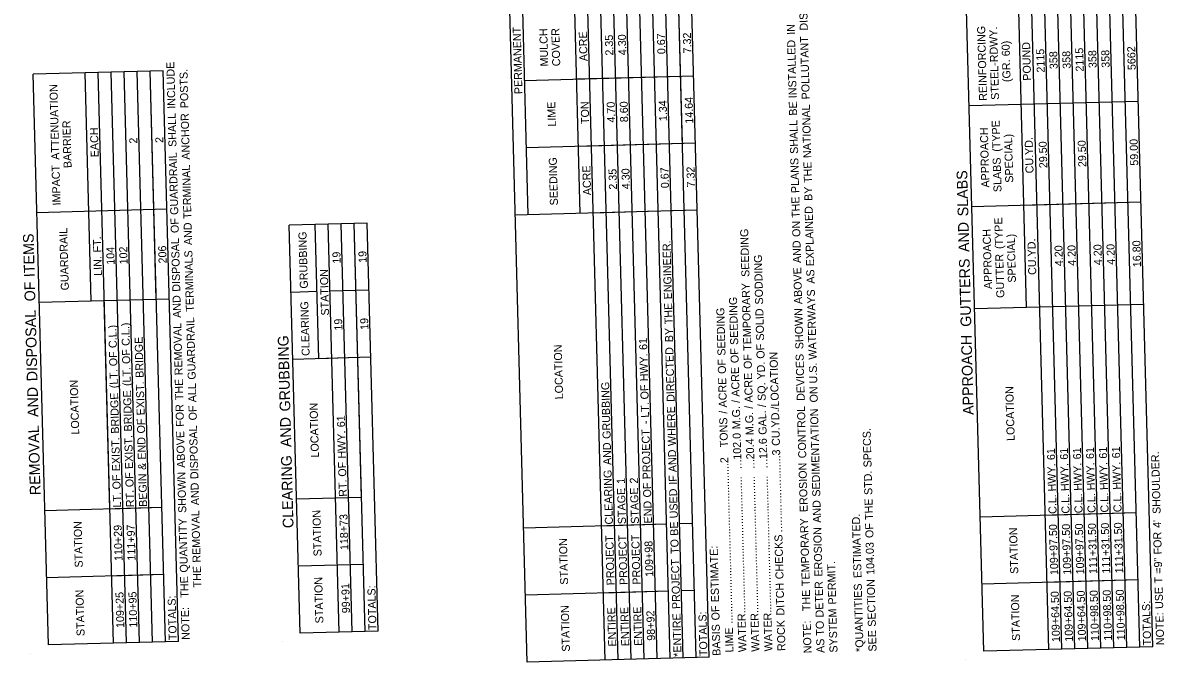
# Model space of a CAD drawing. Extents: x 1930093 to 1931323, y 596452 to 607874.
# Drawn here: x 1930227 to 1931083, y 601457 to 601936 of the extents above; entities that cross this region are included whole.
import ezdxf

# ---------------------------------------------------------------- set-up
doc = ezdxf.new("R2010")
doc.units = 0
doc.layers.add('Default', color=7, linetype='Continuous')
doc.layers.add('R_Border', color=7, linetype='Continuous')

msp = doc.modelspace()

# ---------------------------------------------------------------- linework, layer by layer
at = {"layer": 'Default'}
for p, q in [((1930605.63, 601457.38), (1930573.54, 602652.78)), ((1930606.39, 601792.43), (1930583.29, 602653.05)), ((1930645.38, 601793.48), (1930622.28, 602654.09)), ((1930664.11, 601458.95), (1930632.02, 602654.35)), ((1930673.86, 601459.21), (1930641.77, 602654.62)), ((1930683.6, 601459.47), (1930651.52, 602654.88)), ((1930693.35, 601459.73), (1930661.26, 602655.14)), ((1930703.1, 601459.99), (1930671.01, 602655.4)), ((1930712.84, 601460.26), (1930680.75, 602655.66)), ((1930722.59, 601460.52), (1930690.5, 602655.92)), ((1930732.34, 601460.78), (1930700.25, 602656.19)), ((1930742.08, 601461.04), (1930709.99, 602656.45)), ((1930722, 601845.77), (1930716.17, 602063.11)), ((1930948, 601465.56), (1930933.5, 602006)), ((1930980.11, 601722.94), (1930972.48, 602007.05)), ((1930996.74, 601466.87), (1930982.23, 602007.31)), ((1931006.48, 601467.13), (1930991.97, 602007.57)), ((1931016.23, 601467.39), (1931001.72, 602007.84)), ((1931025.97, 601467.66), (1931011.47, 602008.1)), ((1931035.72, 601467.92), (1931021.21, 602008.36)), ((1931045.47, 601468.18), (1931030.96, 602008.62)), ((1931055.21, 601468.44), (1931040.71, 602008.88)), ((1931064.96, 601468.7), (1931050.45, 602009.14)), ((1931074.71, 601468.96), (1931060.2, 602009.41)), ((1930332.61, 601900.35), (1930235.14, 601897.73)), ((1930278.72, 601727.73), (1930274.13, 601898.78)), ((1930295.35, 601471.66), (1930283.88, 601899.04)), ((1930305.1, 601471.92), (1930293.62, 601899.3)), ((1930314.84, 601472.18), (1930303.37, 601899.56)), ((1930324.59, 601472.44), (1930313.12, 601899.82)), ((1930334.34, 601472.7), (1930322.86, 601900.09)), ((1930325.65, 601796.29), (1930322.86, 601900.09)), ((1930344.08, 601472.96), (1930332.61, 601900.35)), ((1930246.62, 601470.35), (1930235.14, 601897.73)), ((1930730.4, 601896.22), (1930603.7, 601892.82)), ((1930720.66, 601895.96), (1930642.68, 601893.87)), ((1931063.74, 601877.34), (1930937.04, 601873.94)), ((1931063.74, 601877.34), (1930976.03, 601874.99)), ((1930731.75, 601846.03), (1930605.04, 601842.63)), ((1930731.75, 601846.03), (1930644.03, 601843.67)), ((1930335.4, 601796.55), (1930237.93, 601793.93)), ((1930327.45, 601729.04), (1930325.65, 601796.29)), ((1930733.1, 601795.83), (1930596.65, 601792.17)), ((1930733.1, 601795.83), (1930713.6, 601795.31)), ((1931065.77, 601801.81), (1930939.07, 601798.4)), ((1931065.77, 601801.81), (1930978.05, 601799.45)), ((1930703.86, 601795.05), (1930655.12, 601793.74)), ((1930485.67, 601786.1), (1930427.19, 601784.53)), ((1930446.69, 601785.05), (1930427.19, 601784.53)), ((1930435.4, 601478.97), (1930427.19, 601784.53)), ((1930449.38, 601684.66), (1930446.69, 601785.05)), ((1930475.93, 601785.83), (1930456.43, 601785.31)), ((1930464.64, 601479.76), (1930456.43, 601785.31)), ((1930474.38, 601480.02), (1930466.18, 601785.57)), ((1930484.13, 601480.28), (1930475.93, 601785.83)), ((1930481.43, 601580.67), (1930475.93, 601785.83)), ((1930493.88, 601480.54), (1930485.67, 601786.1)), ((1930487.02, 601735.9), (1930457.78, 601735.12)), ((1930487.02, 601735.9), (1930457.78, 601735.12)), ((1930337.2, 601729.3), (1930239.74, 601726.68)), ((1930292.65, 601572.05), (1930288.47, 601727.99)), ((1930337.2, 601729.3), (1930327.45, 601729.04)), ((1930448.04, 601734.85), (1930428.54, 601734.33)), ((1931067.83, 601725.3), (1930941.12, 601721.89)), ((1931067.83, 601725.3), (1930989.85, 601723.2)), ((1930488.37, 601685.71), (1930429.89, 601684.14)), ((1930478.62, 601685.45), (1930449.38, 601684.66)), ((1930331.64, 601573.09), (1930243.92, 601570.74)), ((1930331.64, 601573.09), (1930292.65, 601572.05)), ((1930481.43, 601580.67), (1930432.7, 601579.36)), ((1930481.43, 601580.67), (1930461.94, 601580.15)), ((1931062.27, 601569.09), (1930945.31, 601565.95)), ((1931062.27, 601569.09), (1930994.04, 601567.26)), ((1930710.15, 601560.64), (1930602.94, 601557.77)), ((1930710.15, 601560.64), (1930661.42, 601559.34)), ((1930729.64, 601561.17), (1930719.9, 601560.91)), ((1930729.64, 601561.17), (1930719.9, 601560.91)), ((1930482.78, 601530.48), (1930434.05, 601529.17)), ((1930482.78, 601530.48), (1930463.29, 601529.95)), ((1930332.99, 601522.9), (1930245.27, 601520.54)), ((1930332.99, 601522.9), (1930294, 601521.85)), ((1931063.61, 601518.9), (1930946.66, 601515.76)), ((1931063.61, 601518.9), (1930995.39, 601517.06)), ((1930711.5, 601510.45), (1930604.29, 601507.57)), ((1930711.5, 601510.45), (1930662.76, 601509.14)), ((1930730.99, 601510.97), (1930721.24, 601510.71)), ((1930730.99, 601510.97), (1930721.24, 601510.71)), ((1930493.88, 601480.54), (1930435.4, 601478.97)), ((1930493.88, 601480.54), (1930435.4, 601478.97)), ((1930344.08, 601472.96), (1930246.62, 601470.35)), ((1930344.08, 601472.96), (1930246.62, 601470.35)), ((1931074.71, 601468.96), (1930948, 601465.56)), ((1931074.71, 601468.96), (1930948, 601465.56)), ((1930742.08, 601461.04), (1930605.63, 601457.38)), ((1930742.08, 601461.04), (1930605.63, 601457.38))]:
    msp.add_line(p, q, dxfattribs=at)
at = {"layer": 'R_Border'}
for p, q in [((1930421.91, 601472.76), (1930421.91, 601472.76)), ((1930233.13, 601464.13), (1930233.13, 601464.13)), ((1930934.51, 601459.35), (1930934.51, 601459.35))]:
    msp.add_line(p, q, dxfattribs=at)

# ---------------------------------------------------------------- texts
at = {"layer": 'Default'}
for s, height, p in [(' DISCHARGE', 6, (1930816.12, 601928.2)), ('PERMANENT', 6, (1930602.09, 601882.88)), (' IN', 6, (1930806.45, 601925.08)), ('REINFORCING', 6, (1930950.44, 601877.87)), ('STEEL-RDWY.', 6, (1930959.42, 601878.62)), ('MULCH', 6, (1930621.41, 601903.59)), ('COVER', 6, (1930630.41, 601903.76)), ('ACRE', 6, (1930650.87, 601907.53)), ('2.35', 6, (1930670.26, 601911.73)), ('4.30', 6, (1930680.01, 601912.03)), ('0.67', 6, (1930709.25, 601912.8)), ('7.32', 6, (1930728.74, 601913.35)), (' POLLUTANT', 6, (1930817.51, 601876.68)), (' INSTALLED', 6, (1930807.73, 601877.56)), (' 60)', 6, (1930967.61, 601908.99)), ('POUND', 6, (1930983.42, 601892.92)), ('2115', 6, (1930993.69, 601898.98)), ('2115', 6, (1931022.93, 601899.76)), ('358', 6, (1931032.61, 601902.37)), ('358', 6, (1931042.36, 601902.63)), ('5662', 6, (1931061.91, 601900.85)), ('(GR.', 6, (1930968.07, 601891.88)), ('358', 6, (1931003.37, 601901.59)), ('358', 6, (1931013.12, 601901.85)), (' INCLUDE', 6, (1930341.99, 601869.68)), (' POSTS.', 6, (1930351.73, 601870.08)), (' ATTENUATION', 6, (1930254.93, 601831.43)), ('LIME', 6, (1930627.13, 601858.53)), ('TON', 6, (1930652.13, 601860.49)), ('4.70', 6, (1930671.61, 601861.57)), ('8.60', 6, (1930681.36, 601861.83)), ('1.34', 6, (1930710.6, 601862.62)), ('14.64', 6, (1930730.15, 601860.71)), (' BE', 6, (1930808.08, 601864.5)), (' NATIONAL', 6, (1930818.69, 601832.74)), (' SHALL', 6, (1930342.75, 601841.1)), (' ANCHOR', 6, (1930352.76, 601831.55)), ('BARRIER', 6, (1930264.04, 601827.49)), ('EACH', 6, (1930284.38, 601835.56)), (' SHALL', 6, (1930808.85, 601835.91)), ('APPROACH', 6, (1930952.18, 601812.87)), (' (TYPE', 6, (1930960.53, 601837.48)), ('2', 6, (1930313.37, 601845.79)), ('2', 6, (1930332.86, 601846.3)), ('SPECIAL)', 6, (1930970.09, 601816.51)), ('CU.YD.', 6, (1930985.29, 601823.52)), ('29.50', 6, (1930995.61, 601827.43)), ('29.50', 6, (1931024.85, 601828.22)), ('59.00', 6, (1931063.83, 601829.27)), (' GUARDRAIL', 6, (1930344.12, 601790.18)), ('SEEDING', 6, (1930628.71, 601799.52)), (' PLANS', 6, (1930809.64, 601806.54)), (' THE', 6, (1930819.19, 601814.1)), ('SLABS', 6, (1930961.28, 601809.48)), ('IMPACT', 6, (1930255.79, 601799.48)), (' TERMINAL', 6, (1930353.95, 601787.15)), ('ACRE', 6, (1930653.56, 601807.14)), ('2.35', 6, (1930672.96, 601811.34)), ('4.30', 6, (1930682.7, 601811.64)), ('0.67', 6, (1930711.94, 601812.41)), ('7.32', 6, (1930731.44, 601812.96)), (' SLABS', 8, (1930936.51, 601788.39)), (' BY', 6, (1930819.55, 601800.65)), (' THE', 6, (1930810.14, 601787.9)), (' EXPLAINED', 6, (1930820.86, 601751.73)), (' OF', 6, (1930344.48, 601776.59)), (' ON', 6, (1930810.52, 601773.69)), (' (TYPE', 6, (1930962.48, 601764.66)), ('GUARDRAIL', 6, (1930262, 601735.89)), (' AND', 6, (1930354.48, 601767.57)), ('GRUBBING', 6, (1930441.22, 601737.21)), (' SEEDING', 6, (1930772.31, 601743.73)), (' AND', 8, (1930937.23, 601761.63)), ('APPROACH', 6, (1930954.23, 601736.85)), (' ITEMS', 8, (1930236.48, 601742.84)), (' FT.', 6, (1930286.35, 601762.05)), (' DISPOSAL', 6, (1930345.66, 601732.64)), (' ENGINEER.', 6, (1930714.24, 601726.95)), (' AND', 6, (1930811.04, 601754.11)), ('SPECIAL)', 6, (1930972.1, 601741.66)), ('CU.YD.', 6, (1930987.33, 601747.49)), ('4.20', 6, (1931036.57, 601754.78)), ('4.20', 6, (1931046.32, 601755.05)), ('16.80', 6, (1931065.88, 601753.24)), ('104', 6, (1930296.29, 601755.06)), ('102', 6, (1930306.04, 601755.34)), ('206', 6, (1930335.28, 601756.05)), (' TERMINALS', 6, (1930355.82, 601717.72)), ('19', 6, (1930465.78, 601755.97)), ('19', 6, (1930485.27, 601756.5)), (' SODDING', 6, (1930782.62, 601723.06)), ('GUTTER', 6, (1930963.41, 601730.25)), ('4.20', 6, (1931007.33, 601754)), ('4.20', 6, (1931017.08, 601754.26)), ('LIN.', 6, (1930286.76, 601746.8)), (' ABOVE', 6, (1930811.87, 601723.35)), (' GUTTERS', 8, (1930938.73, 601705.68)), ('STATION', 6, (1930457.07, 601717.03)), (' AS', 6, (1930821.21, 601738.66)), (' OF', 8, (1930236.96, 601724.73)), (' TEMPORARY', 6, (1930773.79, 601688.37)), (' WATERWAYS', 6, (1930822.74, 601681.82)), (' AND', 6, (1930346.19, 601713.07)), ('CLEARING', 6, (1930442.57, 601686.78)), (' SEEDING', 6, (1930763.92, 601692.77)), (' DISPOSAL', 8, (1930238.57, 601664.84)), (' THE', 6, (1930714.74, 601708.3)), (' SEEDING', 6, (1930754.39, 601684.71)), (' SOLID', 6, (1930783.34, 601696.04)), (' SHOWN', 6, (1930812.78, 601689.58)), (' C.L.)', 6, (1930307.74, 601692.09)), (' REMOVAL', 6, (1930347.34, 601670.05)), (' GUARDRAIL', 6, (1930357.19, 601666.79)), ('19', 6, (1930467.12, 601705.78)), ('19', 6, (1930486.62, 601706.31)), (' C.L.)', 6, (1930298.03, 601690.43)), (' GRUBBING', 8, (1930428.19, 601642.26)), (' BY', 6, (1930715.1, 601694.86)), ('APPROACH', 8, (1930940.42, 601642.59)), (' BRIDGE', 6, (1930318.13, 601668.19)), ('LOCATION', 6, (1930632.61, 601654.29)), (' 61', 6, (1930695.75, 601689.04)), (' DIRECTED', 6, (1930716.3, 601650.14)), (' OF', 6, (1930783.71, 601682.45)), (' OF', 6, (1930298.39, 601676.85)), (' OF', 6, (1930308.1, 601678.51)), (' HWY.', 6, (1930696.38, 601665.57)), (' OF', 6, (1930764.29, 601679.19)), (' OF', 6, (1930774.16, 601674.79)), (' CU.YD./LOCATION', 6, (1930795.21, 601617.22)), (' DEVICES', 6, (1930813.81, 601650.9)), (' (LT.', 6, (1930298.84, 601660.36)), (' (LT.', 6, (1930308.55, 601662.02)), (' OF', 6, (1930754.75, 601671.13)), (' ACRE', 6, (1930764.96, 601654.03)), (' YD.', 6, (1930784.12, 601666.89)), (' U.S.', 6, (1930823.22, 601663.93)), ('LOCATION', 6, (1930269.77, 601627.9)), (' THE', 6, (1930347.84, 601651.41)), (' ACRE', 6, (1930755.43, 601645.97)), (' ACRE', 6, (1930774.83, 601649.63)), (' AND', 8, (1930239.29, 601638.08)), (' BRIDGE', 6, (1930299.75, 601626.35)), (' BRIDGE', 6, (1930309.46, 601628)), (' EXIST.', 6, (1930318.89, 601640.05)), (' ALL', 6, (1930357.64, 601649.85)), (' GRUBBING', 6, (1930668.28, 601622.43)), (' OF', 6, (1930696.74, 601651.99)), (' SQ.', 6, (1930784.56, 601650.86)), (' ON', 6, (1930823.6, 601649.72)), ('LOCATION', 6, (1930971.16, 601623.11)), (' FOR', 6, (1930348.38, 601631.51)), ('LOCATION', 6, (1930449.49, 601610.68)), (' LT.', 6, (1930697.11, 601638.29)), (' /', 6, (1930765.09, 601649.37)), (' /', 6, (1930784.68, 601646.2)), (' OF', 6, (1930358, 601636.27)), (' 61', 6, (1930469.12, 601631.18)), (' WHERE', 6, (1930717.19, 601617.07)), (' /', 6, (1930755.55, 601641.31)), (' M.G.', 6, (1930765.62, 601629.62)), (' /', 6, (1930774.96, 601644.97)), (' M.G.', 6, (1930775.49, 601625.22)), (' GAL.', 6, (1930785.24, 601625.51)), (' CONTROL', 6, (1930814.97, 601607.9)), (' SEDIMENTATION', 6, (1930825.49, 601579.16)), ('REMOVAL', 8, (1930240.78, 601582.54)), (' OF', 6, (1930319.25, 601626.47)), (' DISPOSAL', 6, (1930359.18, 601592.32)), (' AND', 8, (1930428.91, 601615.5)), (' -', 6, (1930697.24, 601633.43)), (' TONS', 6, (1930756.23, 601616.14)), (' EXIST.', 6, (1930300.51, 601598.21)), (' EXIST.', 6, (1930310.21, 601599.86)), (' END', 6, (1930319.78, 601606.89)), (' ABOVE', 6, (1930349.2, 601600.75)), (' HWY.', 6, (1930469.76, 601607.7)), (' PROJECT', 6, (1930698.35, 601592.16)), ('102.0', 6, (1930766.17, 601609.06)), ('20.4', 6, (1930775.92, 601609.32)), ('12.6', 6, (1930785.66, 601609.58)), (' SPECS.', 6, (1930863.92, 601601.08)), (' AND', 6, (1930668.8, 601602.86)), (' AND', 6, (1930717.71, 601597.49)), ('.......3', 6, (1930795.76, 601596.65)), (' 61', 6, (1931001.54, 601606.57)), (' 61', 6, (1931011.28, 601606.83)), (' 61', 6, (1931021.03, 601607.09)), (' 61', 6, (1931030.78, 601607.36)), (' 61', 6, (1931040.52, 601607.62)), (' 61', 6, (1931050.27, 601607.88)), ('CLEARING', 8, (1930430.45, 601557.82)), (' ......................................................2', 6, (1930759.78, 601483.94)), ('…', 6, (1930766.37, 601601.66)), ('…', 6, (1930776.12, 601601.93)), ('…', 6, (1930785.86, 601602.19)), ('  SHOULDER.', 6, (1931080.71, 601563.99)), (' OF', 6, (1930310.58, 601586.28)), (' &', 6, (1930319.99, 601599.17)), (' SHOWN', 6, (1930350.11, 601566.98)), (' OF', 6, (1930470.12, 601594.12)), ('CLEARING', 6, (1930669.94, 601560.54)), (' EROSION', 6, (1930816.05, 601567.6)), (' STD.', 6, (1930864.47, 601580.39)), (' HWY.', 6, (1931002.17, 601583.1)), (' HWY.', 6, (1931011.91, 601583.36)), (' HWY.', 6, (1931021.66, 601583.62)), (' HWY.', 6, (1931031.41, 601583.88)), (' HWY.', 6, (1931041.15, 601584.14)), (' HWY.', 6, (1931050.9, 601584.4)), (' OF', 6, (1930300.87, 601584.62)), ('BEGIN', 6, (1930320.67, 601573.77)), (' AND', 6, (1930359.71, 601572.75)), ('RT.', 6, (1930470.46, 601581.35)), (' 1', 6, (1930678.93, 601588.77)), (' 2', 6, (1930688.68, 601589.03)), (' OF', 6, (1930698.71, 601578.57)), (' IF', 6, (1930717.97, 601588.1)), (' WATER..............................................', 6, (1930770.1, 601462.77)), (' WATER..............................................', 6, (1930779.84, 601463.03)), (' WATER..............................................', 6, (1930789.59, 601463.29)), ('…', 6, (1930795.96, 601589.26)), ('LT.', 6, (1930301.18, 601573.25)), ('RT.', 6, (1930310.92, 601573.51)), ('STAGE', 6, (1930679.68, 601560.8)), ('STAGE', 6, (1930689.43, 601561.06)), (' USED', 6, (1930718.64, 601562.93)), ('…', 6, (1930796.16, 601581.86)), ('..', 6, (1930796.27, 601577.94)), ('C.L.', 6, (1931002.56, 601568.46)), ('C.L.', 6, (1931012.31, 601568.72)), ('C.L.', 6, (1931022.05, 601568.99)), ('C.L.', 6, (1931031.8, 601569.25)), ('C.L.', 6, (1931041.55, 601569.51)), ('C.L.', 6, (1931051.29, 601569.77)), ('END', 6, (1930699.18, 601561.33)), ('…', 6, (1930796.46, 601570.54)), (' AND', 6, (1930826.02, 601559.59)), (' THE', 6, (1930864.98, 601561.75)), (' QUANTITY', 6, (1930351.31, 601522.34)), (' REMOVAL', 6, (1930360.86, 601529.73)), ('STATION', 6, (1930451.48, 601536.68)), ('118+73', 6, (1930471.54, 601541.38)), ('.', 6, (1930796.51, 601568.94)), ('…', 6, (1930796.71, 601561.55)), (' TEMPORARY', 6, (1930817.54, 601512.25)), (' ESTIMATED.', 6, (1930856.39, 601518.23)), ('STATION', 6, (1930272.45, 601528.32)), ('110+29', 6, (1930302.25, 601533.27)), ('111+97', 6, (1930311.99, 601533.54)), (' BE', 6, (1930718.99, 601549.87)), ('…', 6, (1930796.9, 601554.15)), (' EROSION', 6, (1930827.1, 601519.29)), (' OF', 6, (1930865.34, 601548.17)), ('STATION', 6, (1930973.83, 601523.53)), ('109+97.50', 6, (1931003.79, 601522.68)), ('109+97.50', 6, (1931013.54, 601522.94)), ('109+97.50', 6, (1931023.28, 601523.2)), ('111+31.50', 6, (1931033.03, 601523.46)), ('111+31.50', 6, (1931042.78, 601523.73)), ('111+31.50', 6, (1931052.52, 601523.99)), (" 4'", 6, (1931080.93, 601555.8)), ('STATION', 6, (1930636.33, 601515.48)), ('PROJECT', 6, (1930671.16, 601514.99)), ('PROJECT', 6, (1930680.91, 601515.26)), ('PROJECT', 6, (1930690.65, 601515.52)), ('109+98', 6, (1930700.25, 601521.35)), (' TO', 6, (1930719.36, 601536.28)), (' CHECKS', 6, (1930797.89, 601517.33)), (' FOR', 6, (1931081.46, 601535.9)), (' ESTIMATE:', 6, (1930749.59, 601500.08)), (' 104.03', 6, (1930866.08, 601520.6)), (' PROJECT', 6, (1930720.46, 601495.01)), (' PERMIT.', 6, (1930837.41, 601498.43)), (' =9"', 6, (1931081.85, 601521.44)), ('THE', 6, (1930361.3, 601513.42)), ('   THE', 6, (1930351.93, 601499.05)), ('STATION', 6, (1930452.83, 601486.49)), ('99+91', 6, (1930472.8, 601494.09)), ('TOTALS:', 6, (1930492.65, 601481.49)), (' DITCH', 6, (1930798.62, 601490.08)), (' DETER', 6, (1930827.92, 601488.67)), ('*QUANTITIES', 6, (1930857.82, 601465.12)), (' SECTION', 6, (1930867.12, 601481.71)), (' T', 6, (1931082.05, 601514.16)), (' USE', 6, (1931082.56, 601495.05)), ('STATION', 6, (1930273.82, 601476.96)), ('109+25', 6, (1930303.6, 601483.06)), ('110+95', 6, (1930313.34, 601483.32)), ('TOTALS:', 6, (1930342.86, 601473.91)), ('   THE', 6, (1930818.16, 601488.95)), ('STATION', 6, (1930975.18, 601473.34)), ('109+64.50', 6, (1931005.14, 601472.48)), ('109+64.50', 6, (1931014.88, 601472.75)), ('109+64.50', 6, (1931024.63, 601473.01)), ('110+98.50', 6, (1931034.38, 601473.27)), ('110+98.50', 6, (1931044.12, 601473.53)), ('110+98.50', 6, (1931053.87, 601473.79)), ('NOTE:', 6, (1930352.6, 601474.17)), ('STATION', 6, (1930637.68, 601465.28)), ('ENTIRE', 6, (1930672.39, 601469.13)), ('ENTIRE', 6, (1930682.14, 601469.39)), ('ENTIRE', 6, (1930691.88, 601469.65)), (' OF', 6, (1930749.95, 601486.5)), ('SYSTEM', 6, (1930838.32, 601464.6)), ('TOTALS:', 6, (1931073.48, 601469.91)), ('98+92', 6, (1930701.53, 601473.52)), ('*ENTIRE', 6, (1930721.36, 601461.46)), ('TOTALS:', 6, (1930740.86, 601461.98)), (' ROCK', 6, (1930799.34, 601463.55)), ('NOTE:', 6, (1930818.83, 601464.08)), (' TO', 6, (1930828.29, 601475.08)), ('NOTE:', 6, (1931083.23, 601470.17)), ('BASIS', 6, (1930750.6, 601462.24)), (' LIME', 6, (1930760.35, 601462.51)), ('SEE', 6, (1930867.56, 601465.38)), ('AS', 6, (1930828.58, 601464.34))]:
    msp.add_text(s, height=height, rotation=91.53769, dxfattribs=at).set_placement(p)

doc.saveas('drawing.dxf')
